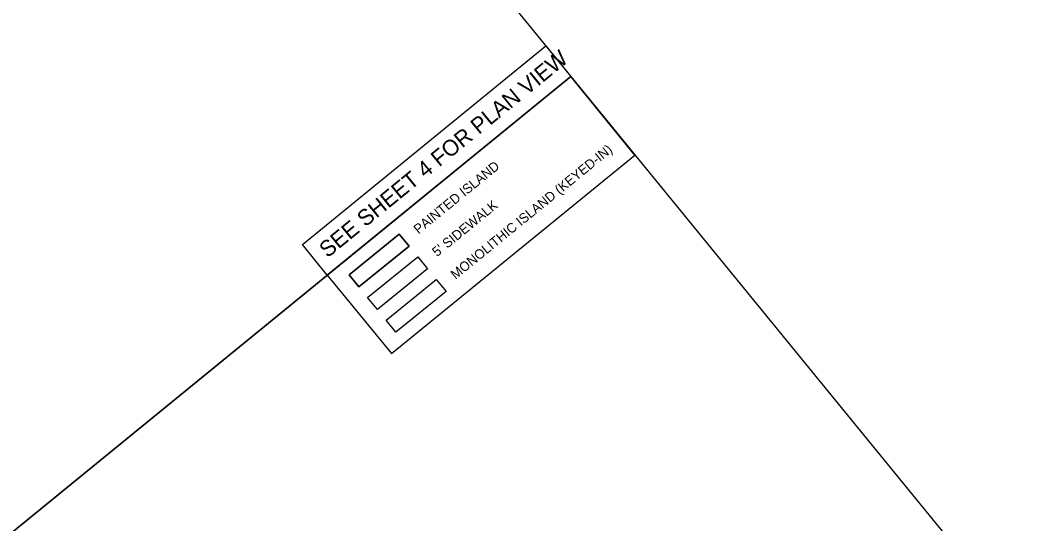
# Model space of a CAD drawing. Extents: x 1528967 to 2322919, y 597128 to 795043.
# Drawn here: x 2322186 to 2322919, y 598094 to 598461 of the extents above; entities that cross this region are included whole.
import ezdxf

# ---------------------------------------------------------------- set-up
doc = ezdxf.new("R2010")
doc.units = 0
for name, color, linetype in [('Default', 7, 'Continuous'), ('Prop Conc 4in Sidewalk', 7, 'Continuous'), ('Prop Conc 5in Monolithic Keyed In Island', 7, 'Continuous'), ('Prop Dimension Text', 7, 'Continuous'), ('Prop Lane Lines', 7, 'Continuous'), ('Sheet Plan CELL', 7, 'Continuous')]:
    doc.layers.add(name, color=color, linetype=linetype)

msp = doc.modelspace()

# ---------------------------------------------------------------- linework, layer by layer
at = {"layer": 'Default'}
for points in [[(2322391.58, 598297.19), (2322568.75, 598441.82), (2322586.87, 598419.63), (2322409.7, 598274.99)], [(2322456.43, 598217.75), (2322633.59, 598362.38), (2322586.86, 598419.62), (2322409.7, 598274.99)]]:
    msp.add_lwpolyline(points, close=True, dxfattribs=at)
at = {"layer": 'Prop Conc 4in Sidewalk'}
msp.add_lwpolyline([(2322439.1, 598258.59), (2322475.54, 598288.34), (2322482.69, 598279.59), (2322446.25, 598249.84)], close=True, dxfattribs=at)
at = {"layer": 'Prop Conc 5in Monolithic Keyed In Island'}
msp.add_lwpolyline([(2322452.57, 598242.09), (2322489.01, 598271.84), (2322496.16, 598263.09), (2322459.71, 598233.34)], close=True, dxfattribs=at)
at = {"layer": 'Prop Lane Lines'}
msp.add_lwpolyline([(2322425.63, 598275.08), (2322462.08, 598304.83), (2322469.22, 598296.08), (2322432.78, 598266.33)], close=True, dxfattribs=at)
msp.add_lwpolyline([(2322432.78, 598266.33), (2322469.22, 598296.08), (2322462.08, 598304.83), (2322425.63, 598275.08), (2322432.78, 598266.33)], dxfattribs=at)
at = {"layer": 'Sheet Plan CELL'}
for points in [[(2321170.32, 597940.94), (2321932.56, 598563.23), (2321956.07, 598534.43), (2322069.68, 598627.18), (2322128.74, 598554.85), (2322190.77, 598605.49), (2322241.95, 598542.8), (2322388.56, 598662.49), (2322586.87, 598419.63), (2321502.31, 597534.26)], [(2321502.31, 597534.26), (2322586.86, 598419.62), (2322918.85, 598012.95), (2321834.3, 597127.59)]]:
    msp.add_lwpolyline(points, close=True, dxfattribs=at)

# ---------------------------------------------------------------- texts
at = {"layer": 'Default'}
msp.add_text('SEE SHEET 4 FOR PLAN VIEW', height=11.6664, rotation=39.22607, dxfattribs=at).set_placement((2322409.88, 598287.03))
at = {"layer": 'Prop Dimension Text'}
for s, p in [('MONOLITHIC ISLAND (KEYED-IN)', (2322503.06, 598271.5)), ('PAINTED ISLAND', (2322476.12, 598304.49)), ("5' SIDEWALK", (2322489.59, 598287.99))]:
    msp.add_text(s, height=7, rotation=39.22799, dxfattribs=at).set_placement(p)

doc.saveas('drawing.dxf')
